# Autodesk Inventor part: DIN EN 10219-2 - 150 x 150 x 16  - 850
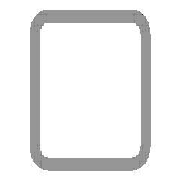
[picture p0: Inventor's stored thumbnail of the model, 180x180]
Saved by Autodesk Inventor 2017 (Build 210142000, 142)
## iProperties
IsCustomPart: 1
Created: 2017-11
Part Number: DIN EN 10219-2 - 150 x 150 x 16  - 850
Material: Steel, Mild
Description: Cold formed welded structural hollow sections of non-alloy and fine grain structural steel
Document SubType Name: Modeling
Standard: DIN
Designer: iusti
Standard Revision: 2006-07
Standards Organization: DIN
Language: en-US
Size Designation: 150 x 150 x 16
Categories: <MemberInstance><Categories><Category DisplayName="Structural Shapes" InternalName="089c4875-fa83-4c05-b084-43b9cc11f5ed" Mnemonic="GRDR"><CategoryParameter Dis
Stock Number: 150 x 150 x 16
Mass: 49891.9 g
Surface Area: 8094.11 cm^2
Volume: 6355.65 cm^3
Density: 7.85 g/cm^3
Appearance: Semi-Polished
_CCFamilyMember: 76
_CCFamilyDisplayName: DIN EN 10219-2 (Square Hollow Section - Cold Formed) - Cold formed welded structural hollow sections of non-alloy and fine grain structural steel
_FrameMemberDoc: Frame Member File
_Version: 15.0.0
_GetPNFromCC: 1
G_L: 850.000 mm
G_W: 150.000 mm
G_H: 150.000 mm
+022A92A4-1665-4D87-A3CD-3B04628A670A+CUTDETAIL1: Cut
+D7EF0BB8-D807-4400-82D5-9F9535CAC881+CUTDETAIL2: Cut
Author: iusti
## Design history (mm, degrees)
node "Start plane"
node "End plane"
sketch "Sketch"
  geometry: L1 (-75, -27)-(-75, 27); L2 (-27, 75)-(27, 75); L3 (75, 27)-(75, -27); L4 (27, -75)-(-27, -75); L5 (-27, 59)-(27, 59); L6 (59, 27)-(59, -27); L7 (27, -59)-(-27, -59); L8 (-59, -27)-(-59, 27); L9 (0, 118.918)-(0, -118.918) reference; L10 (-118.918, 0)-(118.918, 0) reference; A1 r 48 centre (-27, -27) between (-75, -27) and (-27, -75); A2 r 48 centre (-27, 27) between (-27, 75) and (-75, 27); A3 r 48 centre (27, 27) between (75, 27) and (27, 75); A4 r 48 centre (27, -27) between (27, -75) and (75, -27); A5 r 32 centre (-27, 27) between (-27, 59) and (-59, 27); A6 r 32 centre (27, 27) between (59, 27) and (27, 59); A7 r 32 centre (27, -27) between (27, -59) and (59, -27); A8 r 32 centre (-27, -27) between (-59, -27) and (-27, -59)
  constraints: 16 end point, 16 point on circle, 8 centre point, 8 tangent, 4 parallel, 3 equal radius, 2 perpendicular, 7 other
  dimensions: "d7" = 48 radius of A1 (= G_IR); "d10" = 150 distance between parallel lines of L2 L4 (= G_H); "d11" = 150 distance between parallel lines of L1 L3 (= G_W); "d12" = 16 distance between parallel lines of L3 L6 (= G_T); "d15" = 75 distance between parallel lines of L2 L10 (= 0.5 x d10); "d16" = 75 distance between parallel lines of L9 L3 (= 0.5 x d11)
extrude "Body" new body sketch "Sketch" stored distance "d3" = 850 (= G_L); taper "d4" = 0 deg
node "Driven Length"
  sketch "Sketch3"
    geometry: L1 (0, 0)-(10, 0) reference
    constraints: 2 end point, 1 horizontal
  workplane "Work Plane3"
  sketch "Sketch4"
    geometry: L1 (-2, 75)-(12, 75) reference; L2 (-2, 925)-(12, 925) reference
    dimensions: "d18" = 850 distance between parallel lines of L1 L2 (derived)
workplane "Work Plane4"
split "Split1"
workplane "Work Plane5"
split "Split2"
body "Solid1"
other parameters: "G_W" = 150 [user parameter; used in 1 equation term], "G_H" = 150 [user parameter; used in 1 equation term], "G_T" = 16 [user parameter; used in 1 equation term], "G_IR" = 48 [user parameter; used in 1 equation term], "G_L" = 850 (= d18) [user parameter; used in 1 equation term], "G_OFFSET_START" = -75 [user parameter; used in 1 equation term], "G_OFFSET_END" = -75 [user parameter; used in 1 equation term], "d13" = 75 (= -G_OFFSET_START), "d14" = 925 (= G_OFFSET_END + B_L), "d17" = 90 deg
